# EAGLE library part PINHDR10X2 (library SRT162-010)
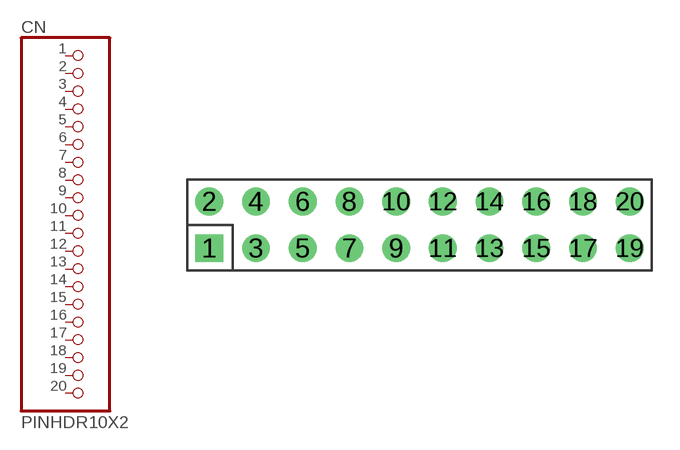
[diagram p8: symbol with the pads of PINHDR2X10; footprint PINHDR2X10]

Designator prefix CN

## PINHDR10X2  [PINHDR2X10]
1  1  pas
2  2  pas
3  3  pas
4  4  pas
5  5  pas
6  6  pas
7  7  pas
8  8  pas
9  9  pas
10  10  pas
11  11  pas
12  12  pas
13  13  pas
14  14  pas
15  15  pas
16  16  pas
17  17  pas
18  18  pas
19  19  pas
20  20  pas

## Footprint PINHDR2X10 (pad centres in mm)
drill 1 square: 1 -11.43,-1.27
drill 1 round: 2 -11.43,1.27; 3 -8.89,-1.27; 4 -8.89,1.27; 5 -6.35,-1.27; 6 -6.35,1.27; 7 -3.81,-1.27; 8 -3.81,1.27; 9 -1.27,-1.27; 10 -1.27,1.27; 11 1.27,-1.27; 12 1.27,1.27; 13 3.81,-1.27; 14 3.81,1.27; 15 6.35,-1.27; 16 6.35,1.27; 17 8.89,-1.27; 18 8.89,1.27; 19 11.43,-1.27; 20 11.43,1.27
